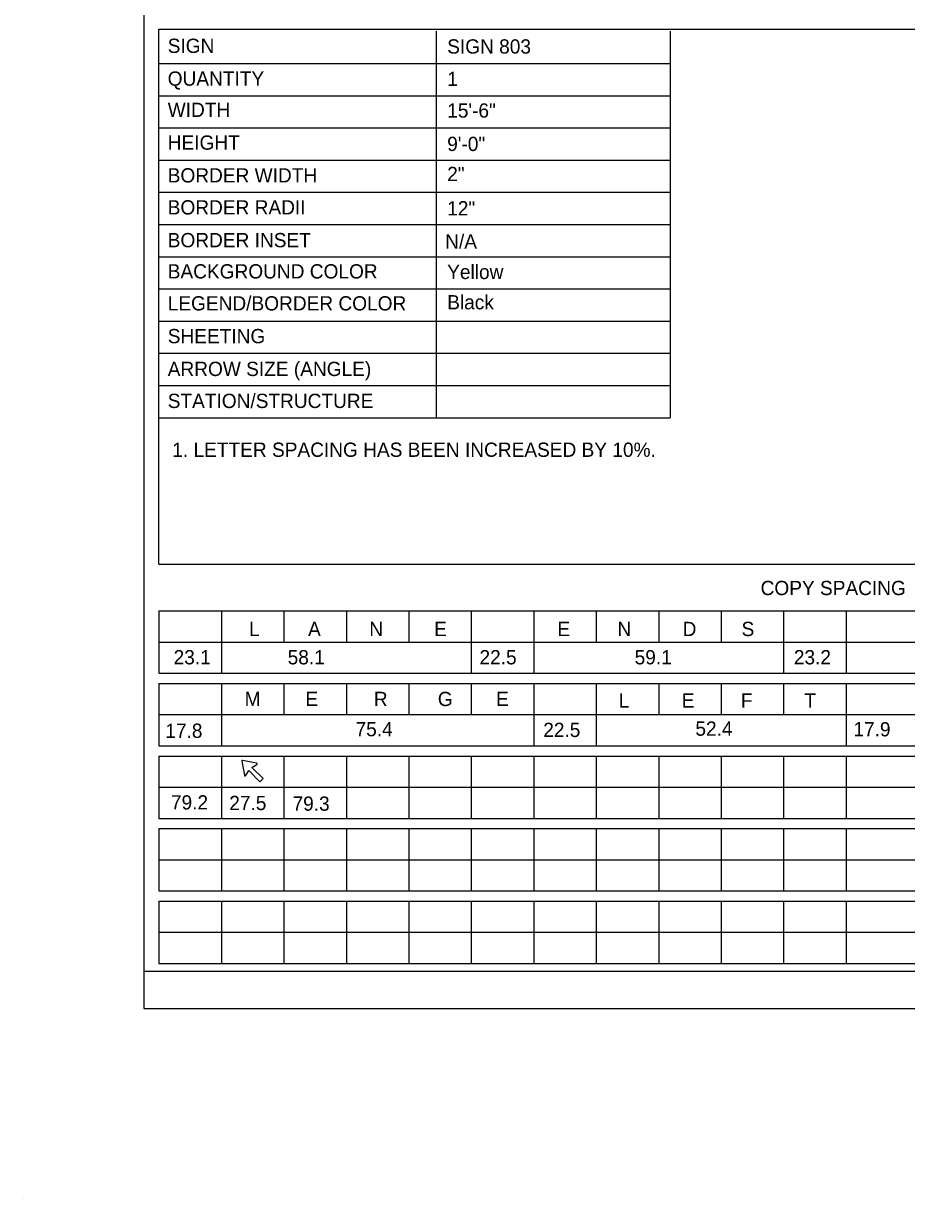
# Model space of a CAD drawing. Extents: x 10268147 to 10268469, y 2141099 to 2141204.
# Drawn here: x 10268147.2 to 10268190.5, y 2141099.3 to 2141156.9 of the extents above; entities that cross this region are included whole.
import ezdxf

# ---------------------------------------------------------------- set-up
doc = ezdxf.new("R2010")
doc.units = 0
for name, color, linetype in [('61', 7, 'Continuous'), ('GSBWFill', 7, 'Continuous'), ('GSColorFill', 7, 'Continuous'), ('GSOutline', 7, 'Continuous'), ('North Arrow', 7, 'Continuous'), ('SheetLinesMisc2_dp', 7, 'Continuous'), ('TextMisc', 7, 'Continuous'), ('TextTitle', 7, 'Continuous')]:
    doc.layers.add(name, color=color, linetype=linetype)

msp = doc.modelspace()

# ---------------------------------------------------------------- linework, layer by layer
at = {"layer": '61'}
for p, q in [((10268153.875, 2141130.399), (10268153.875, 2141156.648)), ((10268153.875, 2141156.648), (10268229.209, 2141156.648)), ((10268167.469, 2141156.54), (10268167.469, 2141137.582)), ((10268178.947, 2141156.54), (10268178.947, 2141137.582)), ((10268153.875, 2141154.96), (10268178.947, 2141154.96)), ((10268153.875, 2141153.38), (10268178.947, 2141153.38)), ((10268153.875, 2141151.8), (10268178.947, 2141151.8)), ((10268153.875, 2141150.22), (10268178.947, 2141150.22)), ((10268153.875, 2141148.641), (10268178.947, 2141148.641)), ((10268153.875, 2141147.061), (10268178.947, 2141147.061)), ((10268153.875, 2141145.481), (10268178.947, 2141145.481)), ((10268153.875, 2141143.901), (10268178.947, 2141143.901)), ((10268153.875, 2141142.322), (10268178.947, 2141142.322)), ((10268153.875, 2141140.742), (10268178.947, 2141140.742)), ((10268153.875, 2141139.162), (10268178.947, 2141139.162)), ((10268153.875, 2141137.582), (10268178.947, 2141137.582)), ((10268153.875, 2141130.399), (10268229.209, 2141130.399)), ((10268153.875, 2141128.105), (10268229.209, 2141128.105)), ((10268153.875, 2141128.105), (10268153.875, 2141125.045)), ((10268156.94, 2141128.105), (10268156.94, 2141125.045)), ((10268160.004, 2141128.105), (10268160.004, 2141126.574)), ((10268163.068, 2141128.105), (10268163.068, 2141126.574)), ((10268166.133, 2141128.105), (10268166.133, 2141126.574)), ((10268169.197, 2141128.105), (10268169.197, 2141125.045)), ((10268172.263, 2141128.105), (10268172.263, 2141125.045)), ((10268175.327, 2141128.105), (10268175.327, 2141126.574)), ((10268178.391, 2141128.105), (10268178.391, 2141126.574)), ((10268181.456, 2141128.105), (10268181.456, 2141126.574)), ((10268184.521, 2141128.105), (10268184.521, 2141125.045)), ((10268187.585, 2141128.105), (10268187.585, 2141125.045)), ((10268153.875, 2141126.574), (10268218.232, 2141126.575)), ((10268153.875, 2141125.045), (10268229.209, 2141125.045)), ((10268153.875, 2141124.546), (10268229.209, 2141124.546)), ((10268153.875, 2141124.546), (10268153.875, 2141121.485)), ((10268156.94, 2141124.546), (10268156.94, 2141121.485)), ((10268160.004, 2141124.546), (10268160.004, 2141123.015)), ((10268163.068, 2141124.546), (10268163.068, 2141123.015)), ((10268166.133, 2141124.546), (10268166.133, 2141123.015)), ((10268169.197, 2141124.546), (10268169.197, 2141123.015)), ((10268172.263, 2141124.546), (10268172.263, 2141121.485)), ((10268175.327, 2141124.546), (10268175.327, 2141121.485)), ((10268178.391, 2141124.546), (10268178.391, 2141123.015)), ((10268181.456, 2141124.546), (10268181.456, 2141123.015)), ((10268184.521, 2141124.546), (10268184.521, 2141123.015)), ((10268187.585, 2141124.546), (10268187.585, 2141121.485)), ((10268153.875, 2141123.015), (10268218.232, 2141123.015)), ((10268153.875, 2141121.485), (10268229.209, 2141121.485)), ((10268153.875, 2141120.986), (10268229.209, 2141120.986)), ((10268153.875, 2141120.986), (10268153.875, 2141117.925)), ((10268156.94, 2141120.986), (10268156.94, 2141117.925)), ((10268160.004, 2141120.986), (10268160.004, 2141117.925)), ((10268163.068, 2141120.986), (10268163.068, 2141117.925)), ((10268166.133, 2141120.986), (10268166.133, 2141117.925)), ((10268169.197, 2141120.986), (10268169.197, 2141117.925)), ((10268172.263, 2141120.986), (10268172.263, 2141117.925)), ((10268175.327, 2141120.986), (10268175.327, 2141117.925)), ((10268178.391, 2141120.986), (10268178.391, 2141117.925)), ((10268181.456, 2141120.986), (10268181.456, 2141117.925)), ((10268184.521, 2141120.986), (10268184.521, 2141117.925)), ((10268187.585, 2141120.986), (10268187.585, 2141117.925)), ((10268153.875, 2141119.455), (10268218.232, 2141119.455)), ((10268153.875, 2141117.925), (10268229.209, 2141117.925)), ((10268153.875, 2141117.426), (10268229.209, 2141117.426)), ((10268153.875, 2141117.426), (10268153.875, 2141114.365)), ((10268156.94, 2141117.426), (10268156.94, 2141114.365)), ((10268160.004, 2141117.426), (10268160.004, 2141114.365)), ((10268163.068, 2141117.426), (10268163.068, 2141114.365)), ((10268166.133, 2141117.426), (10268166.133, 2141114.365)), ((10268169.197, 2141117.426), (10268169.197, 2141114.365)), ((10268172.263, 2141117.426), (10268172.263, 2141114.365)), ((10268175.327, 2141117.426), (10268175.327, 2141114.365)), ((10268178.391, 2141117.426), (10268178.391, 2141114.365)), ((10268181.456, 2141117.426), (10268181.456, 2141114.365)), ((10268184.521, 2141117.426), (10268184.521, 2141114.365)), ((10268187.585, 2141117.426), (10268187.585, 2141114.365)), ((10268153.875, 2141115.896), (10268218.232, 2141115.896)), ((10268153.875, 2141114.365), (10268229.209, 2141114.365)), ((10268153.875, 2141113.866), (10268229.209, 2141113.866)), ((10268153.875, 2141113.866), (10268153.875, 2141110.806)), ((10268156.94, 2141113.866), (10268156.94, 2141110.806)), ((10268160.004, 2141113.866), (10268160.004, 2141110.806)), ((10268163.068, 2141113.866), (10268163.068, 2141110.806)), ((10268166.133, 2141113.866), (10268166.133, 2141110.806)), ((10268169.197, 2141113.866), (10268169.197, 2141110.806)), ((10268172.263, 2141113.866), (10268172.263, 2141110.806)), ((10268175.327, 2141113.866), (10268175.327, 2141110.806)), ((10268178.391, 2141113.866), (10268178.391, 2141110.806)), ((10268181.456, 2141113.866), (10268181.456, 2141110.806)), ((10268184.521, 2141113.866), (10268184.521, 2141110.806)), ((10268187.585, 2141113.866), (10268187.585, 2141110.806)), ((10268153.875, 2141112.337), (10268218.232, 2141112.337)), ((10268153.875, 2141110.806), (10268229.209, 2141110.806))]:
    msp.add_line(p, q, dxfattribs=at)
at = {"layer": 'GSBWFill'}
for p, q in [((10268157.934, 2141120.725), (10268158.066, 2141120.04)), ((10268158.664, 2141120.638), (10268157.978, 2141120.77)), ((10268158.066, 2141120.04), (10268158.066, 2141120.04))]:
    msp.add_line(p, q, dxfattribs=at)
msp.add_lwpolyline([(10268158.135, 2141120.027), (10268158.286, 2141120.273), (10268158.817, 2141119.718), (10268158.986, 2141119.887), (10268158.431, 2141120.418), (10268158.677, 2141120.568)], dxfattribs=at)
for centre, start, end in [((10268157.971, 2141120.732), 79.12281, 190.87719), ((10268158.657, 2141120.601), 301.47194, 79.12281), ((10268158.103, 2141120.047), 190.87719, 328.52807)]:
    msp.add_arc(centre, 0.038, start, end, dxfattribs=at)
at = {"layer": 'GSColorFill'}
for p, q in [((10268157.934, 2141120.725), (10268158.066, 2141120.04)), ((10268158.664, 2141120.638), (10268157.978, 2141120.77)), ((10268158.066, 2141120.04), (10268158.066, 2141120.04))]:
    msp.add_line(p, q, dxfattribs=at)
msp.add_lwpolyline([(10268158.135, 2141120.027), (10268158.286, 2141120.273), (10268158.817, 2141119.718), (10268158.986, 2141119.887), (10268158.431, 2141120.418), (10268158.677, 2141120.568)], dxfattribs=at)
for centre, start, end in [((10268157.971, 2141120.732), 79.12281, 190.87719), ((10268158.657, 2141120.601), 301.47194, 79.12281), ((10268158.103, 2141120.047), 190.87719, 328.52807)]:
    msp.add_arc(centre, 0.038, start, end, dxfattribs=at)
at = {"layer": 'GSOutline'}
for p, q in [((10268157.934, 2141120.725), (10268158.066, 2141120.04)), ((10268158.664, 2141120.638), (10268157.978, 2141120.77)), ((10268158.066, 2141120.04), (10268158.066, 2141120.04))]:
    msp.add_line(p, q, dxfattribs=at)
msp.add_lwpolyline([(10268158.135, 2141120.027), (10268158.286, 2141120.273), (10268158.817, 2141119.718), (10268158.986, 2141119.887), (10268158.431, 2141120.418), (10268158.677, 2141120.568)], dxfattribs=at)
for centre, start, end in [((10268157.971, 2141120.732), 79.12281, 190.87719), ((10268158.657, 2141120.601), 301.47194, 79.12281), ((10268158.103, 2141120.047), 190.87719, 328.52807)]:
    msp.add_arc(centre, 0.038, start, end, dxfattribs=at)
at = {"layer": 'SheetLinesMisc2_dp'}
for p, q in [((10268153.14, 2141203.955), (10268153.14, 2141108.602)), ((10268153.14, 2141110.434), (10268306.32, 2141110.434)), ((10268153.14, 2141108.602), (10268306.32, 2141108.602))]:
    msp.add_line(p, q, dxfattribs=at)
at = {"layer": 'TextTitle'}
msp.add_line((10268147.23, 2141099.278), (10268147.23, 2141099.278), dxfattribs=at)

# ---------------------------------------------------------------- texts
at = {"layer": 'North Arrow'}
for s, p in [('SIGN 803', (10268168.016, 2141155.445)), ('1', (10268168.016, 2141153.857)), ('15\'-6"', (10268168.016, 2141152.304)), ('9\'-0"', (10268168.016, 2141150.665)), ('2"', (10268168.016, 2141149.189)), ('12"', (10268168.016, 2141147.505)), ('N/A', (10268167.917, 2141145.878)), ('Yellow', (10268168.016, 2141144.383)), ('Black', (10268168.016, 2141142.897)), ('L', (10268158.299, 2141126.869)), ('A', (10268161.19, 2141126.869)), ('N', (10268164.194, 2141126.869)), ('E', (10268167.376, 2141126.869)), ('E', (10268173.424, 2141126.869)), ('N', (10268176.366, 2141126.869)), ('D', (10268179.565, 2141126.869)), ('S', (10268182.456, 2141126.869)), ('23.1', (10268154.593, 2141125.482)), ('58.1', (10268160.189, 2141125.482)), ('22.5', (10268169.6, 2141125.482)), ('59.1', (10268177.211, 2141125.482)), ('23.2', (10268185.022, 2141125.482)), ('M', (10268158.078, 2141123.436)), ('E', (10268161.057, 2141123.436)), ('R', (10268164.417, 2141123.436)), ('G', (10268167.555, 2141123.436)), ('E', (10268170.414, 2141123.436)), ('L', (10268176.425, 2141123.361)), ('E', (10268179.52, 2141123.361)), ('F', (10268182.426, 2141123.361)), ('T', (10268185.536, 2141123.361)), ('17.8', (10268154.188, 2141121.876)), ('75.4', (10268163.52, 2141121.955)), ('22.5', (10268172.727, 2141121.918)), ('52.4', (10268180.192, 2141121.98)), ('17.9', (10268187.943, 2141121.949)), ('79.2', (10268154.463, 2141118.362)), ('27.5', (10268157.324, 2141118.332)), ('79.3', (10268160.428, 2141118.301))]:
    msp.add_text(s, height=0.7, dxfattribs=at).set_placement(p)
at = {"layer": 'TextMisc'}
for s, p in [('SIGN', (10268154.305, 2141155.477)), ('QUANTITY', (10268154.305, 2141153.869)), ('WIDTH', (10268154.305, 2141152.337)), ('HEIGHT', (10268154.305, 2141150.729)), ('BORDER WIDTH', (10268154.305, 2141149.122)), ('BORDER RADII', (10268154.305, 2141147.552)), ('BORDER INSET', (10268154.305, 2141145.944)), ('BACKGROUND COLOR', (10268154.305, 2141144.412)), ('LEGEND/BORDER COLOR', (10268154.305, 2141142.843)), ('SHEETING', (10268154.305, 2141141.235)), ('ARROW SIZE (ANGLE)', (10268154.305, 2141139.627)), ('STATION/STRUCTURE', (10268154.305, 2141138.058)), ('1. LETTER SPACING HAS BEEN INCREASED BY 10%.', (10268154.531, 2141135.662)), ('COPY SPACING', (10268183.391, 2141128.878))]:
    msp.add_text(s, height=0.7, dxfattribs=at).set_placement(p)

doc.saveas('drawing.dxf')
